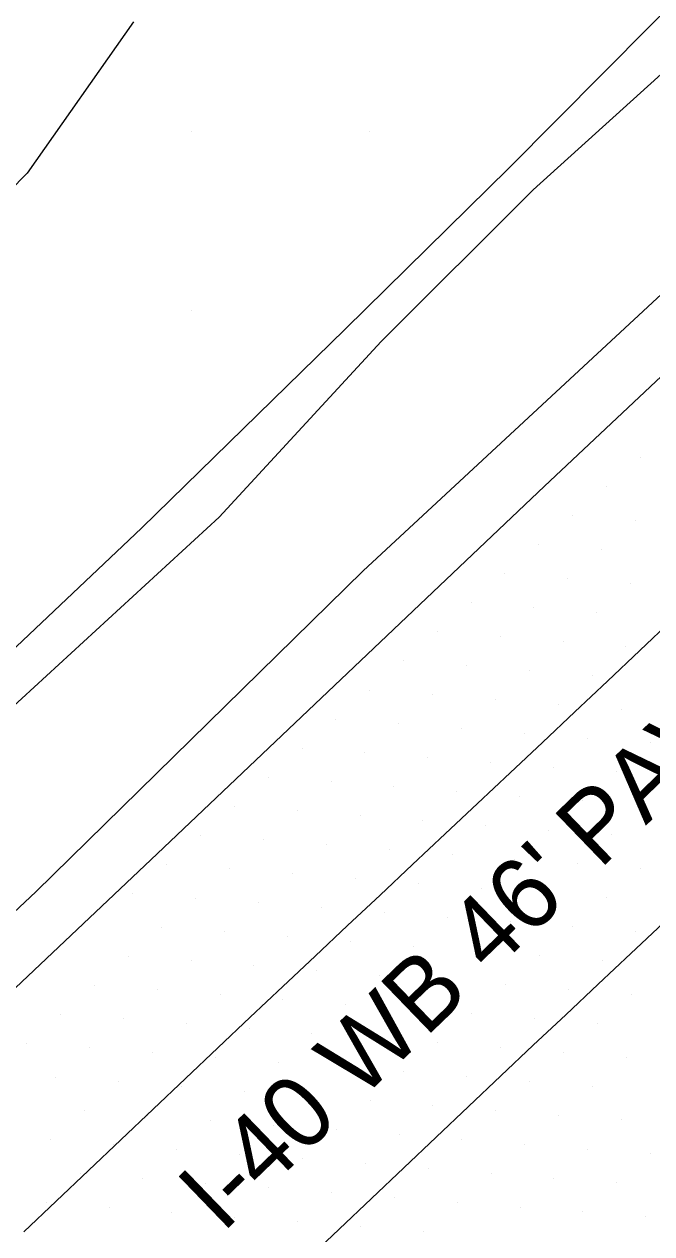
# Model space of a CAD drawing. Extents: x 1548934 to 1561348, y 809680 to 824075.
# Drawn here: x 1552040.6 to 1552075.8, y 810998.2 to 811066.1 of the extents above; entities that cross this region are included whole.
import ezdxf

# ---------------------------------------------------------------- set-up
doc = ezdxf.new("R2010")
doc.units = 0
for name, color, linetype in [('E_NCDOT_Vertical_Profile_Ground_Line', 7, 'Continuous'), ('Exist DTM QL2 LIDAR Elevation Point', 7, 'Continuous'), ('Exist DTM Scan Elevation Point', 7, 'Continuous'), ('Exist Roads EOP Text', 7, 'Continuous'), ('Exist Vegetation Woods Line', 7, 'Continuous'), ('P_RDY_Terminator_Cell', 7, 'Continuous'), ('PH Exist DTM Breakline', 7, 'Continuous')]:
    doc.layers.add(name, color=color, linetype=linetype)

msp = doc.modelspace()

# ---------------------------------------------------------------- linework, layer by layer
at = {"layer": 'E_NCDOT_Vertical_Profile_Ground_Line'}
msp.add_lwpolyline([(1551916.371, 810897.058), (1551938.535, 810917.275), (1551960.652, 810937.518), (1551982.56, 810958.014), (1552004.504, 810978.339), (1552026.319, 810998.917), (1552048.088, 811019.511), (1552069.812, 811040.132), (1552091.656, 811060.693), (1552113.491, 811081.331), (1552135.259, 811101.951), (1552157.034, 811122.672), (1552170.309, 811135.33)], dxfattribs=at)
at = {"layer": 'Exist DTM QL2 LIDAR Elevation Point'}
for p, q in [((1552050.023, 811060.016), (1552050.023, 811060.016)), ((1552060.024, 811060.016), (1552060.024, 811060.016)), ((1552050.023, 811050.015), (1552050.023, 811050.015))]:
    msp.add_line(p, q, dxfattribs=at)
at = {"layer": 'Exist DTM Scan Elevation Point'}
for p, q in [((1552075.178, 811041.731), (1552075.178, 811041.731)), ((1552073.282, 811040.103), (1552073.282, 811040.103)), ((1552071.385, 811038.474), (1552071.385, 811038.474)), ((1552074.91, 811038.206), (1552074.91, 811038.206)), ((1552069.489, 811036.844), (1552069.489, 811036.844)), ((1552073.014, 811036.577), (1552073.014, 811036.577)), ((1552067.592, 811035.216), (1552067.592, 811035.216)), ((1552071.117, 811034.948), (1552071.117, 811034.948)), ((1552074.642, 811034.68), (1552074.642, 811034.68)), ((1552065.696, 811033.587), (1552065.696, 811033.587)), ((1552069.221, 811033.319), (1552069.221, 811033.319)), ((1552072.746, 811033.051), (1552072.746, 811033.051)), ((1552063.8, 811031.958), (1552063.8, 811031.958)), ((1552067.325, 811031.69), (1552067.325, 811031.69)), ((1552070.849, 811031.422), (1552070.849, 811031.422)), ((1552074.374, 811031.154), (1552074.374, 811031.154)), ((1552061.904, 811030.329), (1552061.904, 811030.329)), ((1552065.428, 811030.061), (1552065.428, 811030.061)), ((1552068.953, 811029.793), (1552068.953, 811029.793)), ((1552072.478, 811029.525), (1552072.478, 811029.525)), ((1552060.007, 811028.7), (1552060.007, 811028.7)), ((1552063.532, 811028.432), (1552063.532, 811028.432)), ((1552067.057, 811028.164), (1552067.057, 811028.164)), ((1552070.582, 811027.897), (1552070.582, 811027.897)), ((1552074.107, 811027.629), (1552074.107, 811027.629)), ((1552058.11, 811027.071), (1552058.11, 811027.071)), ((1552061.636, 811026.803), (1552061.636, 811026.803)), ((1552065.161, 811026.536), (1552065.161, 811026.536)), ((1552068.685, 811026.268), (1552068.685, 811026.268)), ((1552072.21, 811026), (1552072.21, 811026)), ((1552075.735, 811025.732), (1552075.735, 811025.732)), ((1552056.215, 811025.443), (1552056.215, 811025.443)), ((1552059.739, 811025.174), (1552059.739, 811025.174)), ((1552063.264, 811024.907), (1552063.264, 811024.907)), ((1552066.789, 811024.639), (1552066.789, 811024.639)), ((1552070.314, 811024.371), (1552070.314, 811024.371)), ((1552054.318, 811023.814), (1552054.318, 811023.814)), ((1552057.843, 811023.546), (1552057.843, 811023.546)), ((1552073.839, 811024.103), (1552073.839, 811024.103)), ((1552061.367, 811023.277), (1552061.367, 811023.277)), ((1552064.893, 811023.01), (1552064.893, 811023.01)), ((1552052.422, 811022.185), (1552052.422, 811022.185)), ((1552068.418, 811022.742), (1552068.418, 811022.742)), ((1552071.943, 811022.474), (1552071.943, 811022.474)), ((1552075.468, 811022.207), (1552075.468, 811022.207)), ((1552055.947, 811021.917), (1552055.947, 811021.917)), ((1552059.471, 811021.649), (1552059.471, 811021.649)), ((1552062.996, 811021.381), (1552062.996, 811021.381)), ((1552066.521, 811021.113), (1552066.521, 811021.113)), ((1552070.046, 811020.845), (1552070.046, 811020.845)), ((1552050.526, 811020.556), (1552050.526, 811020.556)), ((1552054.051, 811020.288), (1552054.051, 811020.288)), ((1552073.571, 811020.578), (1552073.571, 811020.578)), ((1552057.575, 811020.02), (1552057.575, 811020.02)), ((1552061.1, 811019.752), (1552061.1, 811019.752)), ((1552064.625, 811019.484), (1552064.625, 811019.484)), ((1552048.629, 811018.927), (1552048.629, 811018.927)), ((1552068.15, 811019.216), (1552068.15, 811019.216)), ((1552071.675, 811018.949), (1552071.675, 811018.949)), ((1552052.154, 811018.659), (1552052.154, 811018.659)), ((1552055.679, 811018.391), (1552055.679, 811018.391)), ((1552059.204, 811018.123), (1552059.204, 811018.123)), ((1552075.2, 811018.681), (1552075.2, 811018.681)), ((1552062.729, 811017.855), (1552062.729, 811017.855)), ((1552066.253, 811017.587), (1552066.253, 811017.587)), ((1552046.733, 811017.298), (1552046.733, 811017.298)), ((1552050.257, 811017.03), (1552050.257, 811017.03)), ((1552053.782, 811016.762), (1552053.782, 811016.762)), ((1552069.779, 811017.32), (1552069.779, 811017.32)), ((1552073.304, 811017.052), (1552073.304, 811017.052)), ((1552057.308, 811016.494), (1552057.308, 811016.494)), ((1552060.832, 811016.226), (1552060.832, 811016.226)), ((1552048.361, 811015.401), (1552048.361, 811015.401)), ((1552064.357, 811015.959), (1552064.357, 811015.959)), ((1552067.882, 811015.691), (1552067.882, 811015.691)), ((1552071.408, 811015.423), (1552071.408, 811015.423)), ((1552051.886, 811015.133), (1552051.886, 811015.133)), ((1552055.411, 811014.865), (1552055.411, 811014.865)), ((1552074.933, 811015.156), (1552074.933, 811015.156)), ((1552058.936, 811014.598), (1552058.936, 811014.598)), ((1552062.461, 811014.33), (1552062.461, 811014.33)), ((1552065.986, 811014.062), (1552065.986, 811014.062)), ((1552046.465, 811013.772), (1552046.465, 811013.772)), ((1552049.99, 811013.504), (1552049.99, 811013.504)), ((1552069.511, 811013.794), (1552069.511, 811013.794)), ((1552073.036, 811013.527), (1552073.036, 811013.527)), ((1552053.514, 811013.236), (1552053.514, 811013.236)), ((1552057.04, 811012.969), (1552057.04, 811012.969)), ((1552060.565, 811012.701), (1552060.565, 811012.701)), ((1552044.569, 811012.143), (1552044.569, 811012.143)), ((1552064.09, 811012.433), (1552064.09, 811012.433)), ((1552067.615, 811012.165), (1552067.615, 811012.165)), ((1552048.093, 811011.875), (1552048.093, 811011.875)), ((1552051.618, 811011.608), (1552051.618, 811011.608)), ((1552055.143, 811011.34), (1552055.143, 811011.34)), ((1552071.14, 811011.898), (1552071.14, 811011.898)), ((1552074.665, 811011.63), (1552074.665, 811011.63)), ((1552058.668, 811011.072), (1552058.668, 811011.072)), ((1552062.193, 811010.804), (1552062.193, 811010.804)), ((1552042.672, 811010.515), (1552042.672, 811010.515)), ((1552046.197, 811010.246), (1552046.197, 811010.246)), ((1552049.722, 811009.979), (1552049.722, 811009.979)), ((1552065.719, 811010.537), (1552065.719, 811010.537)), ((1552069.244, 811010.269), (1552069.244, 811010.269)), ((1552072.769, 811010.001), (1552072.769, 811010.001)), ((1552053.247, 811009.711), (1552053.247, 811009.711)), ((1552056.772, 811009.443), (1552056.772, 811009.443)), ((1552040.776, 811008.885), (1552040.776, 811008.885)), ((1552044.301, 811008.618), (1552044.301, 811008.618)), ((1552060.297, 811009.175), (1552060.297, 811009.175)), ((1552063.822, 811008.908), (1552063.822, 811008.908)), ((1552067.347, 811008.64), (1552067.347, 811008.64)), ((1552047.826, 811008.35), (1552047.826, 811008.35)), ((1552051.35, 811008.082), (1552051.35, 811008.082)), ((1552070.872, 811008.372), (1552070.872, 811008.372)), ((1552074.397, 811008.104), (1552074.397, 811008.104)), ((1552054.876, 811007.814), (1552054.876, 811007.814)), ((1552058.4, 811007.546), (1552058.4, 811007.546)), ((1552061.926, 811007.279), (1552061.926, 811007.279)), ((1552042.404, 811006.988), (1552042.404, 811006.988)), ((1552045.929, 811006.721), (1552045.929, 811006.721)), ((1552065.451, 811007.011), (1552065.451, 811007.011)), ((1552068.976, 811006.743), (1552068.976, 811006.743)), ((1552049.454, 811006.453), (1552049.454, 811006.453)), ((1552052.979, 811006.185), (1552052.979, 811006.185)), ((1552056.504, 811005.917), (1552056.504, 811005.917)), ((1552072.501, 811006.475), (1552072.501, 811006.475)), ((1552060.029, 811005.65), (1552060.029, 811005.65)), ((1552063.555, 811005.382), (1552063.555, 811005.382)), ((1552044.033, 811005.092), (1552044.033, 811005.092)), ((1552047.558, 811004.824), (1552047.558, 811004.824)), ((1552051.083, 811004.556), (1552051.083, 811004.556)), ((1552067.08, 811005.114), (1552067.08, 811005.114)), ((1552070.605, 811004.847), (1552070.605, 811004.847)), ((1552074.13, 811004.579), (1552074.13, 811004.579)), ((1552054.608, 811004.288), (1552054.608, 811004.288)), ((1552058.133, 811004.021), (1552058.133, 811004.021)), ((1552042.136, 811003.463), (1552042.136, 811003.463)), ((1552045.661, 811003.195), (1552045.661, 811003.195)), ((1552061.658, 811003.753), (1552061.658, 811003.753)), ((1552065.183, 811003.485), (1552065.183, 811003.485)), ((1552068.708, 811003.218), (1552068.708, 811003.218)), ((1552049.186, 811002.927), (1552049.186, 811002.927)), ((1552052.711, 811002.66), (1552052.711, 811002.66)), ((1552072.233, 811002.95), (1552072.233, 811002.95)), ((1552075.759, 811002.682), (1552075.759, 811002.682)), ((1552056.237, 811002.392), (1552056.237, 811002.392)), ((1552059.762, 811002.124), (1552059.762, 811002.124)), ((1552063.287, 811001.856), (1552063.287, 811001.856)), ((1552043.765, 811001.566), (1552043.765, 811001.566)), ((1552047.29, 811001.298), (1552047.29, 811001.298)), ((1552066.812, 811001.589), (1552066.812, 811001.589)), ((1552070.337, 811001.321), (1552070.337, 811001.321)), ((1552050.815, 811001.031), (1552050.815, 811001.031)), ((1552054.34, 811000.763), (1552054.34, 811000.763)), ((1552057.865, 811000.495), (1552057.865, 811000.495)), ((1552073.862, 811001.053), (1552073.862, 811001.053)), ((1552041.868, 810999.937), (1552041.868, 810999.937)), ((1552061.39, 811000.228), (1552061.39, 811000.228)), ((1552064.916, 810999.96), (1552064.916, 810999.96)), ((1552045.394, 810999.669), (1552045.394, 810999.669)), ((1552048.919, 810999.402), (1552048.919, 810999.402)), ((1552052.444, 810999.134), (1552052.444, 810999.134)), ((1552068.441, 810999.692), (1552068.441, 810999.692)), ((1552071.966, 810999.424), (1552071.966, 810999.424)), ((1552075.491, 810999.157), (1552075.491, 810999.157)), ((1552055.969, 810998.866), (1552055.969, 810998.866)), ((1552059.494, 810998.599), (1552059.494, 810998.599)), ((1552063.019, 810998.331), (1552063.019, 810998.331))]:
    msp.add_line(p, q, dxfattribs=at)
at = {"layer": 'Exist Vegetation Woods Line'}
msp.add_lwpolyline([(1552046.764, 811066.187), (1552040.796, 811057.7), (1552033.831, 811050.605), (1552027.198, 811044.144), (1552011.872, 811027.194), (1552000.646, 811017.687), (1551989.121, 811001.199), (1551977.926, 810998.298)], dxfattribs=at)
at = {"layer": 'P_RDY_Terminator_Cell'}
for points in [[(1552040.615, 810998.301), (1552042.428, 811000.022), (1552044.241, 811001.743), (1552046.055, 811003.464), (1552047.868, 811005.185), (1552049.681, 811006.906), (1552051.495, 811008.627), (1552053.311, 811010.345), (1552055.132, 811012.058), (1552056.952, 811013.772), (1552058.773, 811015.485), (1552060.594, 811017.198), (1552062.414, 811018.911), (1552064.235, 811020.625), (1552066.056, 811022.338), (1552067.876, 811024.051), (1552069.697, 811025.764), (1552071.518, 811027.477), (1552073.338, 811029.191), (1552075.155, 811030.908), (1552076.967, 811032.63)], [(1552076.464, 811015.625), (1552074.643, 811013.911), (1552072.823, 811012.198), (1552071.002, 811010.484), (1552069.182, 811008.771), (1552067.361, 811007.058), (1552065.546, 811005.339), (1552063.733, 811003.617), (1552061.92, 811001.896), (1552060.107, 811000.175), (1552058.294, 810998.453), (1552056.481, 810996.732)]]:
    msp.add_lwpolyline(points, dxfattribs=at)
at = {"layer": 'PH Exist DTM Breakline'}
for points in [[(1551976.063, 810969.117), (1551985.645, 810979.795), (1551992.953, 810987.239), (1551997.818, 810992.112), (1552006.041, 810999.753), (1552010.845, 811004.547), (1552015.458, 811008.38), (1552024.583, 811015.752), (1552030.321, 811021.531), (1552038.79, 811029.805), (1552047.218, 811037.777), (1552058.63, 811048.937), (1552067.819, 811057.978), (1552078.405, 811068.681), (1552086.915, 811077.172), (1552097.903, 811087.205), (1552108.724, 811097.642), (1552127.218, 811115.388), (1552138.178, 811125.757), (1552150.17, 811138.937)], [(1551976.365, 810967.374), (1551990.019, 810981.527), (1552001.334, 810991.787), (1552010.226, 811000.09), (1552024.354, 811013.278), (1552036.329, 811024.4), (1552051.566, 811038.401), (1552060.653, 811048.245), (1552069.181, 811056.77), (1552080.239, 811066.769), (1552090.883, 811077.637), (1552102.683, 811090.029), (1552112.717, 811099.388), (1552122.499, 811106.782), (1552140.467, 811123.191), (1552153.599, 811136.588)], [(1552161.51, 811130.572), (1552144.968, 811115.315), (1552129.094, 811100.893), (1552111.266, 811084.329), (1552094.286, 811067.651), (1552076.639, 811051.149), (1552059.635, 811035.387), (1552041.29, 811017.374), (1552022.434, 810999.678), (1552003.445, 810981.098), (1551990.636, 810969.546), (1551980.751, 810963.343)]]:
    msp.add_lwpolyline(points, dxfattribs=at)

# ---------------------------------------------------------------- texts
at = {"layer": 'Exist Roads EOP Text'}
msp.add_text("I-40 WB 46' PAVED", height=4.02, rotation=43.95873, dxfattribs=at).set_placement((1552051.733, 810998.177))

doc.saveas('drawing.dxf')
